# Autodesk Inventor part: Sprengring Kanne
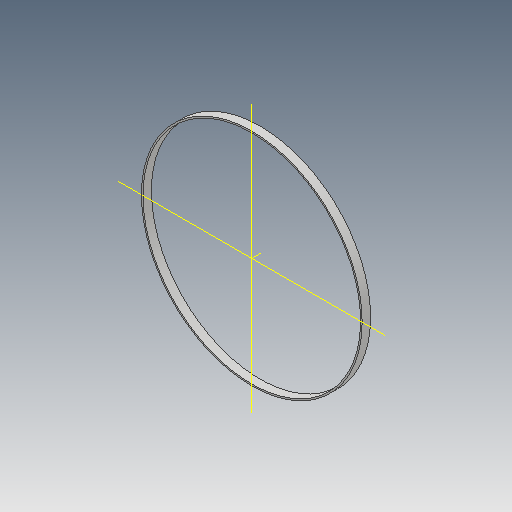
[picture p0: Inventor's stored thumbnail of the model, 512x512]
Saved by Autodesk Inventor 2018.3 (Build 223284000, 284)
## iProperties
Created: 2019-01
Part Number: Sprengring Kanne
Material: Generisch
Document SubType Name: Modeling
Designer: tobiassandmann
Density: 1 g/cm^3
Appearance: Vorgabe
Mass: 2.47086 g
Surface Area: 58.4022 cm^2
Volume: 2.47086 cm^3
Author: tobiassandmann
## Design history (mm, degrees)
sketch "Skizze1"
  geometry: L1 (0, 0)-(0, 71); L2 (0, 71)-(5.5, 71); L3 (5.5, 71)-(5.5, 72); L4 (5.5, 72)-(0, 72); L5 (0, 72)-(0, 71); L6 (0, 0)-(12.993, 0)
  constraints: 12 end point, 3 perpendicular, 2 horizontal, 1 vertical
  dimensions: "d0" = 71 distance of L1.start L1.end; "d1" = 5.5 distance of L1.end L2.end; "d2" = 1 distance of L2.end L3.end
revolve "Umdrehung1" sketch "Skizze1" stored, may be unused: angle "d3" = 90 deg
node "Volumenkörper1"
